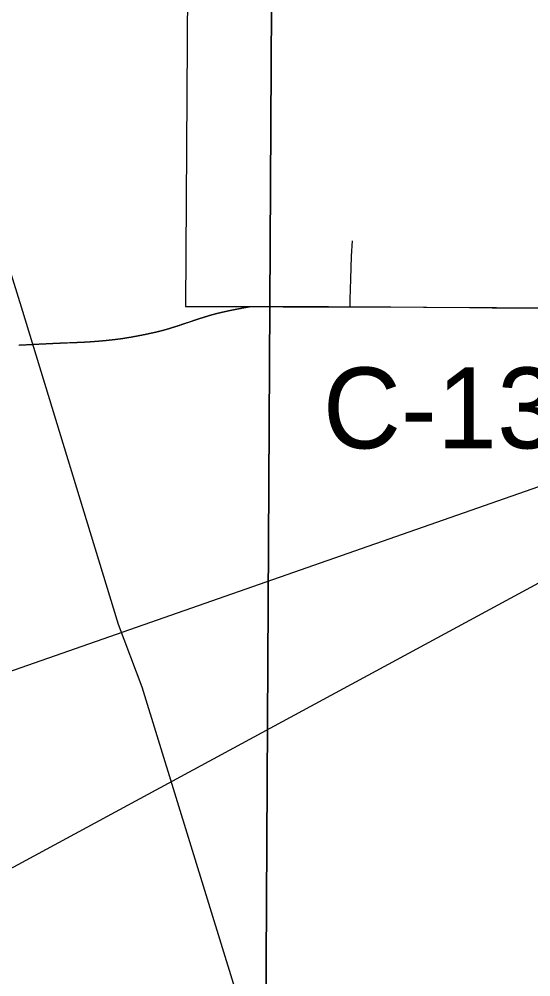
# Model space of a CAD drawing. Extents: x -9.1 to 34, y -3.1 to 22.
# Drawn here: x 5.042 to 5.401, y 17.795 to 18.468 of the extents above; entities that cross this region are included whole.
import ezdxf

# ---------------------------------------------------------------- set-up
doc = ezdxf.new("R2010")
doc.units = 0
for name, color, linetype in [('GM_X_City_Street', 7, 'Continuous'), ('GM_X_Corporation', 7, 'Continuous'), ('GM_X_County_Road', 7, 'Continuous'), ('GM_X_County_Road_Text', 7, 'Continuous'), ('GM_X_Rail_Line', 7, 'Continuous'), ('GM_X_Section', 7, 'Continuous'), ('SH_Text', 7, 'Continuous')]:
    doc.layers.add(name, color=color, linetype=linetype)

msp = doc.modelspace()

# ---------------------------------------------------------------- linework, layer by layer
at = {"layer": 'GM_X_City_Street'}
msp.add_lwpolyline([(5.27411, 18.26585), (5.27426, 18.27102), (5.27467, 18.2851), (5.27509, 18.30141), (5.27587, 18.31207)], dxfattribs=at)
at = {"layer": 'GM_X_Corporation'}
msp.add_lwpolyline([(4.48709, 18.28022), (4.70754, 18.2776), (4.80082, 18.27528), (4.82, 18.31687), (4.83638, 18.35097), (4.87109, 18.42324), (4.90339, 18.49229), (4.93534, 18.5608), (4.96194, 18.61779), (4.96775, 18.61559), (5.16013, 18.52629), (5.15861, 18.26589), (5.2044, 18.26599), (5.22711, 18.26576), (5.2741, 18.26585), (5.53122, 18.26459)], dxfattribs=at)
at = {"layer": 'GM_X_County_Road'}
for points in [[(5.04137, 18.23892), (5.04174, 18.23894), (5.04212, 18.23896), (5.04251, 18.23897), (5.04289, 18.23899), (5.04329, 18.23901), (5.04368, 18.23903), (5.04408, 18.23905), (5.04449, 18.23907), (5.0449, 18.23909), (5.04532, 18.23911), (5.04574, 18.23913), (5.04618, 18.23915), (5.04662, 18.23917), (5.04706, 18.2392), (5.04752, 18.23922), (5.0479, 18.23924), (5.04828, 18.23926), (5.04867, 18.23928), (5.04908, 18.2393), (5.04949, 18.23932), (5.04991, 18.23934), (5.05035, 18.23937), (5.0508, 18.23939), (5.05159, 18.23943), (5.05248, 18.23947), (5.05333, 18.23952), (5.05544, 18.23963), (5.05604, 18.23966), (5.05656, 18.23969), (5.05715, 18.23971), (5.0577, 18.23974), (5.05822, 18.23977), (5.05871, 18.23979), (5.05927, 18.23982), (5.05981, 18.23985), (5.06033, 18.23988), (5.06083, 18.23991), (5.06133, 18.23993), (5.06182, 18.23996), (5.06229, 18.23997), (5.06275, 18.24), (5.06301, 18.24001), (5.06327, 18.24002), (5.06352, 18.24004), (5.06377, 18.24005), (5.06402, 18.24006), (5.06427, 18.24007), (5.06452, 18.24009), (5.06476, 18.2401), (5.065, 18.24011), (5.06524, 18.24012), (5.06548, 18.24013), (5.06572, 18.24014), (5.06595, 18.24015), (5.06618, 18.24016), (5.06641, 18.24017), (5.06665, 18.24019), (5.06687, 18.2402), (5.0671, 18.2402), (5.06733, 18.24022), (5.06756, 18.24023), (5.06778, 18.24024), (5.068, 18.24025), (5.06822, 18.24025), (5.06845, 18.24027), (5.06866, 18.24028), (5.06888, 18.24028), (5.0691, 18.2403), (5.06932, 18.2403), (5.06953, 18.24032), (5.06974, 18.24032), (5.06996, 18.24033), (5.07017, 18.24034), (5.07034, 18.24035), (5.07051, 18.24035), (5.07069, 18.24037), (5.07086, 18.24037), (5.07104, 18.24038), (5.07122, 18.24038), (5.0714, 18.24039), (5.07159, 18.2404), (5.07178, 18.24041), (5.07197, 18.24042), (5.07216, 18.24042), (5.07235, 18.24043), (5.07275, 18.24045), (5.07317, 18.24046), (5.07353, 18.24048), (5.07391, 18.24049), (5.07431, 18.24051), (5.07474, 18.24052), (5.07513, 18.24054), (5.07556, 18.24055), (5.07708, 18.24061), (5.07769, 18.24063), (5.07831, 18.24066), (5.0786, 18.24067), (5.07888, 18.24068), (5.0792, 18.24069), (5.07951, 18.2407), (5.07981, 18.24071), (5.0801, 18.24073), (5.08038, 18.24074), (5.08066, 18.24074), (5.08093, 18.24076), (5.0812, 18.24077), (5.08152, 18.24078), (5.08184, 18.24079), (5.08215, 18.24081), (5.08244, 18.24082), (5.08274, 18.24083), (5.08303, 18.24084), (5.08333, 18.24086), (5.08361, 18.24087), (5.08389, 18.24088), (5.08417, 18.24089), (5.08445, 18.24091), (5.08472, 18.24092), (5.08499, 18.24093), (5.08525, 18.24094), (5.08551, 18.24096), (5.08578, 18.24097), (5.08594, 18.24097), (5.08609, 18.24099), (5.08625, 18.24099), (5.08641, 18.241), (5.08656, 18.24101), (5.08672, 18.24102), (5.08687, 18.24102), (5.08703, 18.24103), (5.08718, 18.24104), (5.08733, 18.24105), (5.08748, 18.24106), (5.08763, 18.24106), (5.08778, 18.24107), (5.08794, 18.24108), (5.08809, 18.24109), (5.08823, 18.24109), (5.08838, 18.2411), (5.08853, 18.24111), (5.08867, 18.24112), (5.08882, 18.24113), (5.08896, 18.24114), (5.08911, 18.24114), (5.08925, 18.24115), (5.0894, 18.24116), (5.08954, 18.24117), (5.08968, 18.24118), (5.08983, 18.24119), (5.08996, 18.2412), (5.09011, 18.2412), (5.09025, 18.24121), (5.09039, 18.24122), (5.09053, 18.24123), (5.09067, 18.24124), (5.09081, 18.24125), (5.09094, 18.24125), (5.09108, 18.24127), (5.09122, 18.24127), (5.09136, 18.24129), (5.09149, 18.24129), (5.09163, 18.2413), (5.09177, 18.24131), (5.0919, 18.24132), (5.09204, 18.24133), (5.09217, 18.24133), (5.09231, 18.24135), (5.09244, 18.24135), (5.09257, 18.24137), (5.0927, 18.24137), (5.09284, 18.24138), (5.09297, 18.24139), (5.0931, 18.2414), (5.09323, 18.24141), (5.09337, 18.24142), (5.0935, 18.24143), (5.09363, 18.24144), (5.09376, 18.24145), (5.09389, 18.24146), (5.09401, 18.24147), (5.09414, 18.24148), (5.09428, 18.24149), (5.09441, 18.2415), (5.09453, 18.24151), (5.09466, 18.24152), (5.09479, 18.24153), (5.09497, 18.24155), (5.09514, 18.24156), (5.09531, 18.24157), (5.09549, 18.24159), (5.09565, 18.2416), (5.09582, 18.24161), (5.09599, 18.24163), (5.09616, 18.24164), (5.09632, 18.24166), (5.09649, 18.24167), (5.09665, 18.24168), (5.09681, 18.2417), (5.09697, 18.24171), (5.09713, 18.24172), (5.09729, 18.24173), (5.09744, 18.24174), (5.0976, 18.24176), (5.09776, 18.24178), (5.09791, 18.24179), (5.09807, 18.2418), (5.09821, 18.24181), (5.09837, 18.24183), (5.09852, 18.24184), (5.09867, 18.24185), (5.09882, 18.24186), (5.09897, 18.24188), (5.09912, 18.24189), (5.09927, 18.24191), (5.09941, 18.24192), (5.09956, 18.24193), (5.0997, 18.24194), (5.09984, 18.24196), (5.09999, 18.24197), (5.10013, 18.24198), (5.10028, 18.24199), (5.10042, 18.24201), (5.10056, 18.24202), (5.1007, 18.24203), (5.10084, 18.24204), (5.10099, 18.24206), (5.10112, 18.24207), (5.10126, 18.24209), (5.1014, 18.2421), (5.10154, 18.24211), (5.10168, 18.24212), (5.10181, 18.24214), (5.10195, 18.24215), (5.10209, 18.24216), (5.10222, 18.24217), (5.10236, 18.24219), (5.10249, 18.2422), (5.10263, 18.24221), (5.10276, 18.24223), (5.10289, 18.24224), (5.10302, 18.24225), (5.10316, 18.24227), (5.10329, 18.24228), (5.10342, 18.24229), (5.10355, 18.2423), (5.10368, 18.24232), (5.10381, 18.24233), (5.10394, 18.24234), (5.10407, 18.24236), (5.1042, 18.24237), (5.10434, 18.24238), (5.10447, 18.2424), (5.1046, 18.24241), (5.10472, 18.24242), (5.10485, 18.24243), (5.10498, 18.24245), (5.10511, 18.24247), (5.10524, 18.24248), (5.10536, 18.24249), (5.10549, 18.2425), (5.10562, 18.24252), (5.10575, 18.24253), (5.10587, 18.24255), (5.10599, 18.24256), (5.10612, 18.24257), (5.10624, 18.24258), (5.10637, 18.2426), (5.10649, 18.24261), (5.10662, 18.24263), (5.10674, 18.24264), (5.10686, 18.24265), (5.10699, 18.24267), (5.10711, 18.24268), (5.10723, 18.2427), (5.10736, 18.24271), (5.10748, 18.24272), (5.1076, 18.24274), (5.10772, 18.24275), (5.10784, 18.24276), (5.10796, 18.24278), (5.10808, 18.2428), (5.10821, 18.24281), (5.10832, 18.24282), (5.10844, 18.24284), (5.10856, 18.24285), (5.10869, 18.24286), (5.1088, 18.24288), (5.10892, 18.24289), (5.10904, 18.24291), (5.10916, 18.24292), (5.10928, 18.24294), (5.10939, 18.24295), (5.10951, 18.24296), (5.10963, 18.24298), (5.10975, 18.24299), (5.10987, 18.24301), (5.10998, 18.24302), (5.1101, 18.24304), (5.11021, 18.24305), (5.11033, 18.24307), (5.11044, 18.24308), (5.11056, 18.2431), (5.11067, 18.24311), (5.11079, 18.24312), (5.1109, 18.24314), (5.11102, 18.24316), (5.11113, 18.24317), (5.11125, 18.24319), (5.11136, 18.2432), (5.11147, 18.24322), (5.11159, 18.24323), (5.1117, 18.24325), (5.11182, 18.24326), (5.11193, 18.24328), (5.11211, 18.2433), (5.11229, 18.24332), (5.11247, 18.24335), (5.11265, 18.24337), (5.11283, 18.2434), (5.11301, 18.24343), (5.11319, 18.24345), (5.11338, 18.24348), (5.11356, 18.2435), (5.11374, 18.24353), (5.11392, 18.24355), (5.1141, 18.24358), (5.11428, 18.24361), (5.11447, 18.24363), (5.11465, 18.24367), (5.11484, 18.24369), (5.11502, 18.24371), (5.1152, 18.24375), (5.11538, 18.24377), (5.11557, 18.2438), (5.11576, 18.24383), (5.11594, 18.24386), (5.11612, 18.24388), (5.11631, 18.24391), (5.1165, 18.24394), (5.11668, 18.24397), (5.11687, 18.244), (5.11705, 18.24403), (5.11724, 18.24406), (5.11743, 18.24409), (5.11761, 18.24412), (5.1178, 18.24415), (5.11799, 18.24418), (5.11818, 18.24421), (5.11837, 18.24424), (5.11855, 18.24427), (5.11875, 18.24431), (5.11893, 18.24434), (5.11912, 18.24437), (5.11931, 18.2444), (5.1195, 18.24444), (5.1197, 18.24447), (5.11988, 18.2445), (5.12007, 18.24453), (5.12027, 18.24457), (5.12046, 18.2446), (5.12065, 18.24463), (5.12085, 18.24467), (5.12104, 18.2447), (5.12123, 18.24473), (5.12142, 18.24476), (5.12162, 18.2448), (5.12181, 18.24483), (5.12201, 18.24487), (5.1222, 18.2449), (5.12239, 18.24494), (5.12259, 18.24498), (5.12278, 18.24501), (5.12298, 18.24504), (5.12318, 18.24508), (5.12337, 18.24512), (5.12357, 18.24516), (5.12377, 18.24519), (5.12397, 18.24522), (5.12417, 18.24526), (5.12437, 18.2453), (5.12457, 18.24534), (5.12477, 18.24537), (5.12496, 18.24541), (5.12516, 18.24545), (5.12536, 18.24549), (5.12556, 18.24553), (5.12577, 18.24557), (5.12597, 18.2456), (5.12617, 18.24565), (5.12637, 18.24568), (5.12657, 18.24572), (5.12677, 18.24577), (5.12698, 18.2458), (5.12718, 18.24585), (5.12739, 18.24588), (5.12759, 18.24593), (5.1278, 18.24596), (5.128, 18.24601), (5.12821, 18.24605), (5.12842, 18.24609), (5.12862, 18.24613), (5.12883, 18.24618), (5.12904, 18.24622), (5.12925, 18.24626), (5.12946, 18.2463), (5.12967, 18.24634), (5.12988, 18.24639), (5.13009, 18.24643), (5.1303, 18.24647), (5.13051, 18.24652), (5.13073, 18.24656), (5.13094, 18.2466), (5.13115, 18.24665), (5.13137, 18.2467), (5.13158, 18.24674), (5.13179, 18.24678), (5.13201, 18.24683), (5.13222, 18.24688), (5.13244, 18.24693), (5.13266, 18.24697), (5.13287, 18.24702), (5.1331, 18.24706), (5.13332, 18.24711), (5.13353, 18.24716), (5.13376, 18.24721), (5.13397, 18.24726), (5.1342, 18.24731), (5.13442, 18.24735), (5.13465, 18.2474), (5.13487, 18.24745), (5.13509, 18.2475), (5.13532, 18.24755), (5.13555, 18.2476), (5.13577, 18.24765), (5.136, 18.2477), (5.13623, 18.24775), (5.13646, 18.2478), (5.13669, 18.24785), (5.13692, 18.2479), (5.13715, 18.24796), (5.13739, 18.24801), (5.13762, 18.24806), (5.13769, 18.24808), (5.13777, 18.2481), (5.13783, 18.24811), (5.13791, 18.24813), (5.13798, 18.24815), (5.13805, 18.24816), (5.13813, 18.24818), (5.1382, 18.24819), (5.13827, 18.24821), (5.13834, 18.24823), (5.13842, 18.24824), (5.13849, 18.24826), (5.13856, 18.24828), (5.13864, 18.24829), (5.13871, 18.24831), (5.13878, 18.24833), (5.13885, 18.24835), (5.13893, 18.24837), (5.139, 18.24838), (5.13908, 18.2484), (5.13915, 18.24842), (5.13923, 18.24844), (5.13929, 18.24846), (5.13937, 18.24847), (5.13944, 18.24849), (5.13952, 18.24851), (5.13959, 18.24852), (5.13967, 18.24854), (5.13974, 18.24856), (5.13982, 18.24858), (5.13989, 18.2486), (5.13996, 18.24862), (5.14004, 18.24864), (5.14011, 18.24865), (5.14019, 18.24867), (5.14026, 18.24869), (5.14034, 18.24871), (5.14041, 18.24873), (5.14049, 18.24875), (5.14056, 18.24877), (5.14064, 18.24879), (5.14071, 18.2488), (5.14079, 18.24882), (5.14086, 18.24884), (5.14093, 18.24886), (5.14101, 18.24888), (5.14109, 18.2489), (5.14116, 18.24892), (5.14124, 18.24894), (5.14131, 18.24896), (5.14139, 18.24898), (5.14147, 18.249), (5.14154, 18.24902), (5.14162, 18.24903), (5.14169, 18.24906), (5.14177, 18.24908), (5.14185, 18.2491), (5.14192, 18.24911), (5.142, 18.24914), (5.14208, 18.24916), (5.14215, 18.24918), (5.14223, 18.2492), (5.14231, 18.24922), (5.14238, 18.24924), (5.14246, 18.24926), (5.14254, 18.24928), (5.14262, 18.2493), (5.14269, 18.24932), (5.14277, 18.24934), (5.14285, 18.24936), (5.14293, 18.24938), (5.143, 18.24941), (5.14308, 18.24943), (5.14316, 18.24945), (5.14324, 18.24947), (5.14331, 18.24949), (5.14339, 18.24951), (5.14348, 18.24953), (5.14355, 18.24956), (5.14363, 18.24957), (5.14371, 18.2496), (5.14379, 18.24962), (5.14387, 18.24964), (5.14395, 18.24966), (5.14402, 18.24969), (5.1441, 18.2497), (5.14418, 18.24973), (5.14426, 18.24975), (5.14434, 18.24977), (5.14442, 18.2498), (5.1445, 18.24982), (5.14458, 18.24984), (5.14466, 18.24987), (5.14474, 18.24988), (5.14482, 18.24991), (5.1449, 18.24993), (5.14499, 18.24995), (5.14507, 18.24998), (5.14515, 18.25), (5.14523, 18.25002), (5.14531, 18.25005), (5.14539, 18.25007), (5.14547, 18.2501), (5.14555, 18.25011), (5.14563, 18.25014), (5.14571, 18.25016), (5.1458, 18.25019), (5.14588, 18.25021), (5.14596, 18.25024), (5.14604, 18.25026), (5.14613, 18.25028), (5.14621, 18.25031), (5.14629, 18.25033), (5.14637, 18.25036), (5.14646, 18.25038), (5.14654, 18.25041), (5.14671, 18.25046), (5.14687, 18.25051), (5.14704, 18.25056), (5.14721, 18.25061), (5.14738, 18.25066), (5.14755, 18.25071), (5.14764, 18.25074), (5.14773, 18.25076), (5.14781, 18.25079), (5.1479, 18.25081), (5.14799, 18.25084), (5.14807, 18.25087), (5.14825, 18.25092), (5.14843, 18.25097), (5.14861, 18.25103), (5.14879, 18.25108), (5.14897, 18.25114), (5.14915, 18.2512), (5.14933, 18.25125), (5.14951, 18.25131), (5.1497, 18.25136), (5.14988, 18.25142), (5.15006, 18.25148), (5.15025, 18.25154), (5.15043, 18.25159), (5.15063, 18.25166), (5.15081, 18.25172), (5.15101, 18.25177), (5.1512, 18.25184), (5.15139, 18.2519), (5.15158, 18.25196), (5.15178, 18.25202), (5.15198, 18.25208), (5.15217, 18.25215), (5.15237, 18.25222), (5.15258, 18.25228), (5.15278, 18.25235), (5.15299, 18.25241), (5.15319, 18.25248), (5.1534, 18.25255), (5.15361, 18.25262), (5.1538, 18.25268), (5.154, 18.25274), (5.15419, 18.25281), (5.15439, 18.25287), (5.15459, 18.25294), (5.1548, 18.253), (5.155, 18.25307), (5.15521, 18.25314), (5.15542, 18.25322), (5.15563, 18.25328), (5.15585, 18.25336), (5.15606, 18.25343), (5.15629, 18.2535), (5.15651, 18.25358), (5.15674, 18.25366), (5.15698, 18.25373), (5.15718, 18.25381), (5.15739, 18.25387), (5.15761, 18.25395), (5.15783, 18.25402), (5.15806, 18.2541), (5.15829, 18.25417), (5.15853, 18.25426), (5.15878, 18.25434), (5.15923, 18.2545), (5.15974, 18.25466), (5.16023, 18.25483), (5.16153, 18.25527), (5.16192, 18.2554), (5.16227, 18.25552), (5.16266, 18.25565), (5.16302, 18.25578), (5.16337, 18.25589), (5.1637, 18.256), (5.1639, 18.25607), (5.16409, 18.25614), (5.16429, 18.2562), (5.16447, 18.25626), (5.16466, 18.25632), (5.16484, 18.25638), (5.16502, 18.25645), (5.16519, 18.2565), (5.16537, 18.25656), (5.16554, 18.25662), (5.16571, 18.25668), (5.16588, 18.25673), (5.16604, 18.25679), (5.16621, 18.25684), (5.16637, 18.25689), (5.16653, 18.25695), (5.16673, 18.25702), (5.16693, 18.25708), (5.16712, 18.25714), (5.16732, 18.25721), (5.16751, 18.25727), (5.1677, 18.25734), (5.16789, 18.2574), (5.16808, 18.25746), (5.16826, 18.25752), (5.16844, 18.25758), (5.16863, 18.25763), (5.16881, 18.2577), (5.16898, 18.25775), (5.16916, 18.25781), (5.16934, 18.25787), (5.16952, 18.25793), (5.16969, 18.25798), (5.16987, 18.25804), (5.17004, 18.25809), (5.17021, 18.25814), (5.17038, 18.2582), (5.17055, 18.25825), (5.17072, 18.2583), (5.17088, 18.25836), (5.17105, 18.25841), (5.17122, 18.25847), (5.17138, 18.25852), (5.17155, 18.25857), (5.17171, 18.25862), (5.17187, 18.25867), (5.17203, 18.25872), (5.1722, 18.25877), (5.17229, 18.2588), (5.1724, 18.25883), (5.1725, 18.25886), (5.1726, 18.25889), (5.1727, 18.25893), (5.1728, 18.25896), (5.1729, 18.25899), (5.173, 18.25902), (5.1731, 18.25905), (5.1732, 18.25907), (5.1733, 18.25911), (5.17339, 18.25914), (5.17349, 18.25917), (5.17359, 18.2592), (5.17369, 18.25922), (5.17378, 18.25926), (5.17388, 18.25929), (5.17397, 18.25932), (5.17407, 18.25934), (5.17417, 18.25937), (5.17426, 18.2594), (5.17436, 18.25943), (5.17446, 18.25946), (5.17455, 18.25949), (5.17464, 18.25952), (5.17474, 18.25954), (5.17484, 18.25957), (5.17493, 18.2596), (5.17502, 18.25963), (5.17512, 18.25965), (5.17522, 18.25968), (5.17531, 18.25971), (5.1754, 18.25974), (5.17549, 18.25976), (5.17559, 18.25979), (5.17568, 18.25982), (5.17577, 18.25985), (5.17587, 18.25987), (5.17596, 18.2599), (5.17605, 18.25993), (5.17614, 18.25995), (5.17623, 18.25998), (5.17633, 18.26001), (5.17642, 18.26003), (5.17651, 18.26006), (5.1766, 18.26008), (5.17669, 18.26011), (5.17678, 18.26014), (5.17687, 18.26016), (5.17697, 18.26019), (5.17705, 18.26021), (5.17715, 18.26024), (5.17723, 18.26026), (5.17733, 18.26029), (5.17741, 18.26031), (5.17751, 18.26034), (5.17759, 18.26036), (5.17769, 18.26039), (5.17778, 18.26041), (5.17786, 18.26044), (5.17796, 18.26046), (5.17804, 18.26049), (5.17813, 18.26051), (5.17822, 18.26054), (5.17831, 18.26056), (5.1784, 18.26058), (5.17849, 18.26061), (5.17858, 18.26063), (5.17866, 18.26065), (5.17875, 18.26068), (5.17884, 18.2607), (5.17892, 18.26073), (5.17902, 18.26075), (5.1791, 18.26077), (5.17919, 18.2608), (5.17928, 18.26082), (5.17937, 18.26085), (5.17945, 18.26086), (5.17954, 18.26089), (5.17963, 18.26091), (5.17971, 18.26093), (5.1798, 18.26096), (5.17989, 18.26098), (5.17997, 18.261), (5.18006, 18.26103), (5.18014, 18.26104), (5.18023, 18.26107), (5.18032, 18.26109), (5.1804, 18.26111), (5.18049, 18.26114), (5.18057, 18.26116), (5.18066, 18.26118), (5.18075, 18.2612), (5.18083, 18.26122), (5.18091, 18.26124), (5.181, 18.26127), (5.18109, 18.26129), (5.18117, 18.26131), (5.18125, 18.26133), (5.18134, 18.26135), (5.18142, 18.26137), (5.18151, 18.26139), (5.18159, 18.26141), (5.18168, 18.26144), (5.18176, 18.26145), (5.18185, 18.26147), (5.18193, 18.2615), (5.18201, 18.26152), (5.18209, 18.26154), (5.18218, 18.26155), (5.18226, 18.26158), (5.18235, 18.2616), (5.18243, 18.26162), (5.18252, 18.26164), (5.1826, 18.26165), (5.18268, 18.26168), (5.18276, 18.2617), (5.18285, 18.26172), (5.18293, 18.26173), (5.18301, 18.26175), (5.18309, 18.26177), (5.18317, 18.26179), (5.18326, 18.26182), (5.18334, 18.26183), (5.18342, 18.26185), (5.18351, 18.26187), (5.18359, 18.26189), (5.18367, 18.26191), (5.18383, 18.26195), (5.184, 18.26198), (5.18416, 18.26201), (5.18431, 18.26205), (5.18447, 18.26209), (5.18464, 18.26213), (5.1848, 18.26216), (5.18496, 18.2622), (5.18512, 18.26223), (5.18528, 18.26227), (5.18544, 18.26231), (5.1856, 18.26234), (5.18577, 18.26238), (5.18592, 18.26241), (5.18608, 18.26245), (5.18624, 18.26249), (5.18641, 18.26252), (5.18657, 18.26255), (5.18673, 18.26259), (5.18689, 18.26262), (5.18705, 18.26266), (5.18721, 18.2627), (5.18738, 18.26273), (5.18754, 18.26277), (5.1877, 18.2628), (5.18786, 18.26283), (5.18802, 18.26287), (5.18818, 18.2629), (5.18834, 18.26294), (5.1885, 18.26298), (5.18866, 18.26301), (5.18882, 18.26305), (5.18898, 18.26308), (5.18915, 18.26311), (5.18931, 18.26314), (5.18947, 18.26318), (5.18963, 18.26321), (5.18979, 18.26325), (5.18995, 18.26328), (5.19012, 18.26331), (5.19028, 18.26335), (5.19044, 18.26338), (5.1906, 18.26342), (5.19076, 18.26345), (5.19092, 18.26348), (5.19108, 18.26352), (5.19125, 18.26355), (5.19141, 18.26358), (5.19157, 18.26362), (5.19173, 18.26365), (5.19189, 18.26368), (5.19205, 18.26372), (5.19222, 18.26375), (5.19238, 18.26378), (5.19254, 18.26381), (5.19271, 18.26385), (5.19287, 18.26388), (5.19303, 18.26391), (5.19319, 18.26394), (5.19335, 18.26398), (5.19351, 18.26401), (5.19368, 18.26404), (5.19384, 18.26407), (5.194, 18.2641), (5.19416, 18.26413), (5.19432, 18.26416), (5.19448, 18.2642), (5.19465, 18.26423), (5.19481, 18.26426), (5.19497, 18.26429), (5.19513, 18.26433), (5.1953, 18.26436), (5.19546, 18.26439), (5.19562, 18.26442), (5.19578, 18.26445), (5.19594, 18.26448), (5.19611, 18.26451), (5.19627, 18.26454), (5.19643, 18.26457), (5.19659, 18.26461), (5.19675, 18.26464), (5.19692, 18.26467), (5.19708, 18.2647), (5.19724, 18.26473), (5.1974, 18.26475), (5.19757, 18.26479), (5.19773, 18.26482), (5.19789, 18.26485), (5.19805, 18.26488), (5.19822, 18.26491), (5.19838, 18.26494), (5.19854, 18.26497), (5.1987, 18.265), (5.19886, 18.26503), (5.19903, 18.26506), (5.19919, 18.26509), (5.19936, 18.26511), (5.19952, 18.26515), (5.19968, 18.26518), (5.19984, 18.2652), (5.2, 18.26523), (5.20016, 18.26526), (5.20033, 18.26529), (5.20049, 18.26532), (5.20065, 18.26535), (5.20082, 18.26538), (5.20098, 18.26541), (5.20114, 18.26544), (5.20131, 18.26546), (5.20147, 18.26549), (5.20163, 18.26552), (5.20179, 18.26555), (5.20196, 18.26558), (5.20212, 18.26561), (5.20228, 18.26564), (5.20244, 18.26566), (5.20261, 18.26569), (5.20277, 18.26572), (5.20293, 18.26575), (5.2031, 18.26577), (5.20326, 18.2658), (5.20343, 18.26583), (5.20359, 18.26586), (5.20375, 18.26589), (5.20391, 18.26591), (5.20408, 18.26594), (5.20424, 18.26597), (5.2044, 18.266)], [(5.2044, 18.266), (5.24898, 18.26593), (5.2591, 18.26593), (5.27411, 18.26585)], [(5.27411, 18.26585), (5.30285, 18.2657), (5.32812, 18.26563), (5.35814, 18.2653)], [(5.35814, 18.2653), (5.37395, 18.26513), (5.41416, 18.26479), (5.43893, 18.26483), (5.46984, 18.26501), (5.50386, 18.26474), (5.53122, 18.26459)]]:
    msp.add_lwpolyline(points, dxfattribs=at)
at = {"layer": 'GM_X_Rail_Line'}
msp.add_lwpolyline([(5.35605, 17.26065), (5.18547, 17.8126), (5.12815, 17.99868), (5.11158, 18.04263), (5.04323, 18.26559), (4.98762, 18.44451), (4.9489, 18.57172), (4.88796, 18.76688), (4.82092, 18.98452), (4.78778, 19.09094), (4.76193, 19.17487)], dxfattribs=at)
at = {"layer": 'GM_X_Section'}
for points in [[(4.22542, 18.77097), (5.22068, 18.771), (5.21493, 17.76405), (4.21254, 17.77165)], [(5.22068, 18.771), (6.22532, 18.76489), (6.22405, 17.76169), (5.21493, 17.76405)]]:
    msp.add_lwpolyline(points, close=True, dxfattribs=at)
at = {"layer": 'SH_Text'}
msp.add_lwpolyline([(4.5258, 17.83175), (5.76106, 18.26339), (4.5258, 17.59575)], close=True, dxfattribs=at)

# ---------------------------------------------------------------- texts
at = {"layer": 'GM_X_County_Road_Text'}
msp.add_text('C-138', height=0.056818, rotation=0.00001, dxfattribs=at).set_placement((5.25501, 18.16637))

doc.saveas('drawing.dxf')
